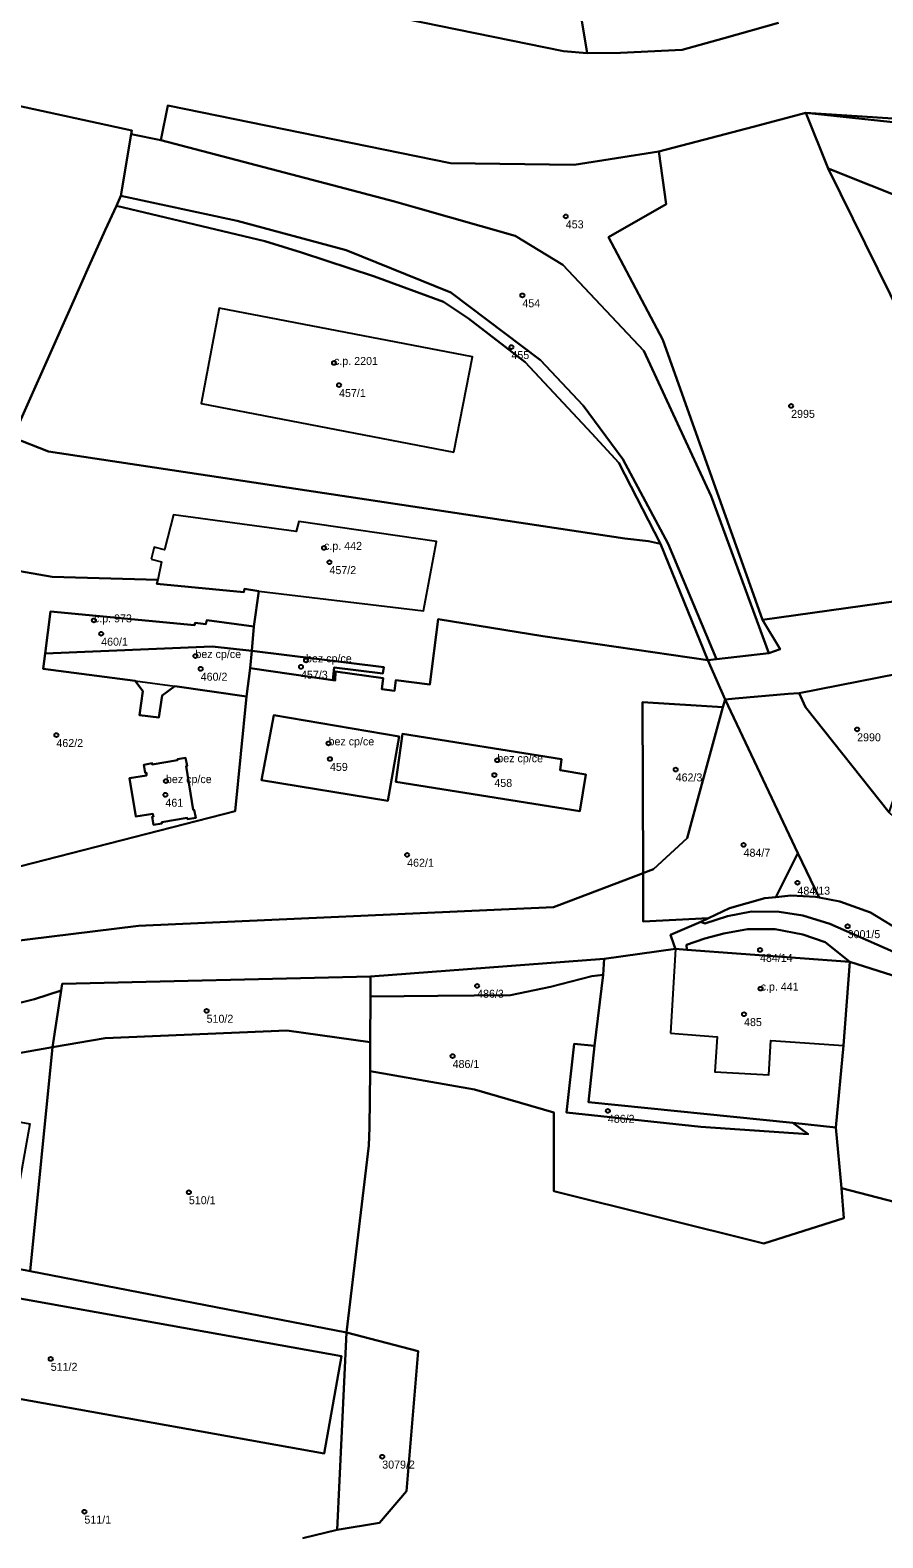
# Model space of a CAD drawing. Extents: x -878211 to -870363, y -1058464 to -1052522.
# Drawn here: x -874127.9 to -874021, y -1056425.6 to -1056236.7 of the extents above; entities that cross this region are included whole.
import ezdxf

# ---------------------------------------------------------------- set-up
doc = ezdxf.new("R2010")
doc.units = 0
for name, color, linetype in [('Vrstva 50', 7, 'Continuous'), ('Vrstva 51', 7, 'Continuous'), ('Vrstva 52', 7, 'Continuous')]:
    doc.layers.add(name, color=color, linetype=linetype)

msp = doc.modelspace()

# ---------------------------------------------------------------- linework, layer by layer
at = {"layer": 'Vrstva 50'}
for centre in [(-874060.75, -1056259.99994), (-874066.19, -1056269.88994), (-874067.56, -1056276.37994), (-874089.79, -1056278.35994), (-874089.16, -1056281.13994), (-874032.51, -1056283.74994), (-874091.04, -1056301.52994), (-874090.36, -1056303.32994), (-874119.88, -1056310.61994), (-874118.97, -1056312.29994), (-874107.16, -1056315.08994), (-874106.5, -1056316.68994), (-874093.93, -1056316.43994), (-874093.3, -1056315.62994), (-874024.24, -1056324.27994), (-874124.58, -1056324.99994), (-874090.48, -1056326.02994), (-874090.3, -1056327.98994), (-874069.33, -1056328.14994), (-874069.7, -1056329.99994), (-874046.98, -1056329.30994), (-874110.85, -1056330.75994), (-874110.92, -1056332.47994), (-874038.47, -1056338.74994), (-874080.63, -1056339.99994), (-874031.72, -1056343.49994), (-874025.43, -1056348.94994), (-874036.41, -1056351.91994), (-874071.86, -1056356.41994), (-874036.33, -1056356.76994), (-874105.76, -1056359.54994), (-874038.41, -1056359.96994), (-874074.93, -1056365.21994), (-874055.48, -1056372.08994), (-874107.98, -1056382.28994), (-874125.29, -1056403.16994), (-874083.75, -1056415.41994), (-874121.07, -1056422.31994)]:
    msp.add_circle(centre, 0.25, dxfattribs=at)
at = {"layer": 'Vrstva 51'}
for points in [[(-874059.11, -1056233.23), (-874064.36, -1056233.25), (-874065.94, -1056233.26), (-874106.31, -1056225.83), (-874114.6, -1056224.35), (-874120.49, -1056226.51), (-874127.68, -1056227.83), (-874142.65, -1056236.19), (-874138.49, -1056244.16), (-874126.68, -1056232.13), (-874109.62, -1056229.34), (-874061.05, -1056239.3), (-874058.08, -1056239.54)], [(-874079.57, -1056258.86), (-874067.1, -1056262.42), (-874061.1, -1056266.05), (-874050.97, -1056276.86), (-874042.54, -1056295.05), (-874035.32, -1056314.71), (-874033.87, -1056314.23), (-874036.08, -1056310.57), (-874048.58, -1056275.46), (-874055.38, -1056262.61), (-874048.16, -1056258.46), (-874049.09, -1056251.87), (-874059.72, -1056253.54), (-874075.21, -1056253.33), (-874110.6, -1056246.1), (-874111.48, -1056250.46), (-874089.99, -1056256.06), (-874082.23, -1056258.11)], [(-874049.09, -1056251.87), (-874048.16, -1056258.46), (-874055.38, -1056262.61), (-874048.58, -1056275.46), (-874036.08, -1056310.57), (-874017.31, -1056307.91), (-874017.32, -1056309.62), (-874007.97, -1056309.02), (-874002.08, -1056307.95), (-873993.82, -1056304.25), (-873999.93, -1056301.64), (-874017.02, -1056276.02), (-874027.88, -1056253.98), (-874030.65, -1056247.03), (-874037.26, -1056248.76), (-874042.53, -1056250.15)], [(-873797.24, -1056300.31), (-873896.52, -1056284.41), (-873978.91, -1056271.72), (-873994.77, -1056260.17), (-874013.14, -1056248.9), (-874030.65, -1056247.03), (-874027.88, -1056253.98), (-874017.16, -1056258.25), (-874000.36, -1056269.81), (-873980.12, -1056280.18), (-873897.49, -1056292.51), (-873788.4, -1056310.11), (-873790.45, -1056308.07), (-873795.73, -1056302.13)], [(-873797.24, -1056300.31), (-873819.79, -1056279.67), (-873848.06, -1056269.06), (-873855.46, -1056263.87), (-873865.64, -1056260.91), (-873876.47, -1056261.7), (-873908.1, -1056261.09), (-873916.49, -1056260.24), (-873969.22, -1056250.9), (-873996.05, -1056249.29), (-874030.65, -1056247.03), (-874013.14, -1056248.9), (-873994.77, -1056260.17), (-873978.91, -1056271.72), (-873896.52, -1056284.41)], [(-874116.49, -1056257.43), (-874101.93, -1056260.55), (-874088.26, -1056264.21), (-874075.17, -1056269.51), (-874063.93, -1056278.01), (-874058.57, -1056283.7), (-874053.6, -1056290.43), (-874047.93, -1056301.04), (-874041.87, -1056315.47), (-874035.32, -1056314.71), (-874042.54, -1056295.05), (-874050.97, -1056276.86), (-874061.1, -1056266.05), (-874067.1, -1056262.42), (-874079.57, -1056258.86), (-874082.23, -1056258.11), (-874089.99, -1056256.06), (-874111.48, -1056250.46), (-874115.23, -1056249.69)], [(-874017.16, -1056258.25), (-874027.88, -1056253.98), (-874017.02, -1056276.02), (-873999.93, -1056301.64), (-873993.82, -1056304.25), (-873980.12, -1056280.18), (-874000.36, -1056269.81)], [(-874117.05, -1056258.67), (-874098.46, -1056263.09), (-874093.85, -1056264.5), (-874084.7, -1056267.52), (-874076.09, -1056270.72), (-874072.94, -1056272.77), (-874065.86, -1056278.28), (-874057.5, -1056287.22), (-874054.11, -1056290.88), (-874048.88, -1056301.03), (-874042.96, -1056315.61), (-874041.87, -1056315.47), (-874047.93, -1056301.04), (-874053.6, -1056290.43), (-874058.57, -1056283.7), (-874063.93, -1056278.01), (-874075.17, -1056269.51), (-874088.26, -1056264.21), (-874101.93, -1056260.55), (-874116.49, -1056257.43)], [(-874122.76, -1056271.35), (-874123.64, -1056273.32), (-874130.06, -1056287.71), (-874125.56, -1056289.45), (-874053.37, -1056300.34), (-874050.4, -1056300.68), (-874048.88, -1056301.03), (-874054.11, -1056290.88), (-874057.5, -1056287.22), (-874065.86, -1056278.28), (-874072.94, -1056272.77), (-874076.09, -1056270.72), (-874084.7, -1056267.52), (-874093.85, -1056264.5), (-874098.46, -1056263.09), (-874117.05, -1056258.67), (-874118.47, -1056261.73), (-874120.51, -1056266.29), (-874121.47, -1056268.45)], [(-874100.74, -1056320.17), (-874102.19, -1056334.51), (-874138.68, -1056343.87), (-874136.61, -1056351.17), (-874136.39, -1056351.63), (-874114.3, -1056348.91), (-874062.31, -1056346.55), (-874061.62, -1056346.29), (-874051.06, -1056342.3), (-874051.12, -1056320.88), (-874041.05, -1056321.49), (-874040.79, -1056320.53), (-874042.96, -1056315.61), (-874063.63, -1056312.59), (-874076.74, -1056310.47), (-874077.79, -1056318.66), (-874082.04, -1056318.09), (-874082.2, -1056319.45), (-874083.82, -1056319.24), (-874083.65, -1056317.85), (-874089.61, -1056317.03), (-874089.66, -1056318.17), (-874089.96, -1056318.13), (-874100.28, -1056316.61)], [(-874107.29, -1056311.22), (-874125.32, -1056309.5), (-874125.99, -1056314.77), (-874105.06, -1056313.91), (-874100.1, -1056314.42), (-874099.84, -1056311.4), (-874105.75, -1056310.58), (-874105.84, -1056311.09), (-874107.2, -1056310.91)], [(-874113.77, -1056319.48), (-874114.18, -1056322.48), (-874111.73, -1056322.78), (-874111.32, -1056320.04), (-874109.74, -1056318.87), (-874100.74, -1056320.17), (-874100.28, -1056316.61), (-874100.1, -1056314.42), (-874105.06, -1056313.91), (-874125.99, -1056314.77), (-874126.24, -1056316.71), (-874114.71, -1056318.19)], [(-874089.96, -1056318.13), (-874089.76, -1056316.53), (-874083.67, -1056317.29), (-874083.57, -1056316.5), (-874100.1, -1056314.42), (-874100.28, -1056316.61)], [(-874031.51, -1056319.74), (-874030.73, -1056321.5), (-874020.22, -1056334.71), (-874016.52, -1056323.42), (-874016.65, -1056316.8)], [(-874044.19, -1056332.98), (-874041.05, -1056321.49), (-874051.12, -1056320.88), (-874051.06, -1056342.3), (-874050.43, -1056342.06), (-874049.76, -1056341.81), (-874045.54, -1056337.91)], [(-874034.44, -1056345.3), (-874031.66, -1056339.78), (-874040.79, -1056320.53), (-874041.05, -1056321.49), (-874044.19, -1056332.98), (-874045.54, -1056337.91), (-874049.76, -1056341.81), (-874050.43, -1056342.06), (-874051.06, -1056342.3), (-874051.04, -1056348.34), (-874042.85, -1056347.92), (-874040.22, -1056346.68), (-874035.79, -1056345.45)], [(-874081.62, -1056325.16), (-874097.34, -1056322.49), (-874098.87, -1056330.66), (-874083.03, -1056333.25)], [(-874081.62, -1056325.16), (-874083.03, -1056333.25), (-874098.87, -1056330.66), (-874097.34, -1056322.49)], [(-874061.47, -1056329.38), (-874061.27, -1056328.02), (-874081.2, -1056324.85), (-874082.05, -1056330.85), (-874058.98, -1056334.53), (-874058.24, -1056329.94)], [(-874061.47, -1056329.38), (-874058.24, -1056329.94), (-874058.98, -1056334.53), (-874082.05, -1056330.85), (-874081.2, -1056324.85), (-874061.27, -1056328.02)], [(-874113.31, -1056329.71), (-874113.28, -1056330.04), (-874115.42, -1056330.4), (-874114.64, -1056335.2), (-874112.48, -1056334.85), (-874112.42, -1056335.2), (-874112.58, -1056335.22), (-874112.41, -1056336.24), (-874111.39, -1056336.07), (-874111.36, -1056335.92), (-874108.19, -1056335.38), (-874108.17, -1056335.52), (-874107.11, -1056335.37), (-874107.3, -1056334.34), (-874107.43, -1056334.34), (-874108.34, -1056328.88), (-874108.2, -1056328.85), (-874108.39, -1056327.83), (-874109.42, -1056327.99), (-874109.42, -1056328.13), (-874112.58, -1056328.67), (-874112.6, -1056328.52), (-874113.64, -1056328.7), (-874113.46, -1056329.73)], [(-874113.31, -1056329.71), (-874113.46, -1056329.73), (-874113.64, -1056328.7), (-874112.6, -1056328.52), (-874112.58, -1056328.67), (-874109.42, -1056328.13), (-874109.42, -1056327.99), (-874108.39, -1056327.83), (-874108.2, -1056328.85), (-874108.34, -1056328.88), (-874107.43, -1056334.34), (-874107.3, -1056334.34), (-874107.11, -1056335.37), (-874108.17, -1056335.52), (-874108.19, -1056335.38), (-874111.36, -1056335.92), (-874111.39, -1056336.07), (-874112.41, -1056336.24), (-874112.58, -1056335.22), (-874112.42, -1056335.2), (-874112.48, -1056334.85), (-874114.64, -1056335.2), (-874115.42, -1056330.4), (-874113.28, -1056330.04)], [(-874034.44, -1056345.3), (-874032.55, -1056345.1), (-874029.45, -1056345.28), (-874028.99, -1056345.36), (-874031.66, -1056339.78)], [(-874042.85, -1056347.92), (-874043.84, -1056348.38), (-874043.31, -1056348.59), (-874040.47, -1056347.68), (-874037.48, -1056347.09), (-874034.01, -1056347.14), (-874031.03, -1056347.6), (-874027.65, -1056348.65), (-874011.71, -1056355.68), (-874010.74, -1056355.42), (-874013.39, -1056353.61), (-874018.19, -1056349.9), (-874022.58, -1056347.23), (-874026.42, -1056345.83), (-874028.99, -1056345.36), (-874029.45, -1056345.28), (-874032.55, -1056345.1), (-874034.44, -1056345.3), (-874035.79, -1056345.45), (-874040.22, -1056346.68)], [(-874045.59, -1056351.89), (-874025.16, -1056353.39), (-874028.26, -1056350.94), (-874031.05, -1056349.98), (-874034.51, -1056349.3), (-874037.96, -1056349.3), (-874040.93, -1056349.84), (-874043.34, -1056350.5), (-874045.62, -1056351.28)], [(-874025.94, -1056363.91), (-874025.16, -1056353.39), (-874045.59, -1056351.89), (-874047.01, -1056351.79), (-874055.94, -1056353.02), (-874056.06, -1056355.02), (-874057.15, -1056363.95), (-874057.92, -1056371), (-874032.3, -1056373.57), (-874026.9, -1056374.16)], [(-874055.94, -1056353.02), (-874085.23, -1056355.23), (-874085.23, -1056357.74), (-874076.8, -1056357.66), (-874067.66, -1056357.57), (-874062.67, -1056356.52), (-874057.5, -1056355.2), (-874056.06, -1056355.02)], [(-873996.96, -1056386.93), (-873996.37, -1056385.7), (-874001.54, -1056383.61), (-873998.1, -1056375.5), (-873993.66, -1056365.6), (-874016.36, -1056356.19), (-874025.16, -1056353.39), (-874025.94, -1056363.91), (-874026.9, -1056374.16), (-874026.22, -1056381.77), (-873998.01, -1056389.1)], [(-874085.23, -1056355.23), (-874123.85, -1056356.15), (-874123.97, -1056357), (-874125.06, -1056364.12), (-874118.48, -1056362.96), (-874095.71, -1056362.03), (-874085.26, -1056363.47), (-874085.23, -1056357.74)], [(-874026.22, -1056381.77), (-874026.9, -1056374.16), (-874032.3, -1056373.57), (-874030.38, -1056375.02), (-874043.83, -1056374.1), (-874060.65, -1056372.28), (-874059.69, -1056363.68), (-874057.15, -1056363.95), (-874056.06, -1056355.02), (-874057.5, -1056355.2), (-874062.67, -1056356.52), (-874067.66, -1056357.57), (-874076.8, -1056357.66), (-874085.23, -1056357.74), (-874085.26, -1056363.47), (-874085.27, -1056367.09), (-874072.2, -1056369.4), (-874062.24, -1056372.28), (-874062.24, -1056382.16), (-874035.94, -1056388.69), (-874025.92, -1056385.52)], [(-874125.06, -1056364.12), (-874127.85, -1056392.18), (-874088.23, -1056399.85), (-874085.45, -1056376.44), (-874085.34, -1056374.16), (-874085.27, -1056367.09), (-874085.26, -1056363.47), (-874095.71, -1056362.03), (-874118.48, -1056362.96)], [(-874032.3, -1056373.57), (-874057.92, -1056371), (-874057.15, -1056363.95), (-874059.69, -1056363.68), (-874060.65, -1056372.28), (-874043.83, -1056374.1), (-874030.38, -1056375.02)], [(-874131.1, -1056391.55), (-874127.85, -1056392.18), (-874125.06, -1056364.12), (-874145.98, -1056367.81), (-874154.41, -1056387.04), (-874143.29, -1056389.19), (-874140.06, -1056371.5), (-874127.89, -1056373.71)], [(-874131.1, -1056391.55), (-874143.29, -1056389.19), (-874145.95, -1056403.75), (-874133.69, -1056406.04), (-874133.94, -1056407.33), (-874091.04, -1056415), (-874088.86, -1056402.82), (-874131.74, -1056395.13)], [(-874089.4, -1056424.57), (-874084.09, -1056423.71), (-874080.72, -1056419.74), (-874079.26, -1056402.21), (-874088.23, -1056399.85)]]:
    msp.add_lwpolyline(points, close=True, dxfattribs=at)
for points in [[(-874034.08, -1056235.73), (-874040.92, -1056237.64), (-874046.18, -1056239.11), (-874053.89, -1056239.5), (-874058.08, -1056239.54), (-874061.05, -1056239.3), (-874109.62, -1056229.34)], [(-874126.68, -1056232.13), (-874138.49, -1056244.16), (-874136.86, -1056244.52), (-874115.14, -1056249.21), (-874115.23, -1056249.69), (-874111.48, -1056250.46), (-874110.6, -1056246.1), (-874075.21, -1056253.33), (-874059.72, -1056253.54), (-874049.09, -1056251.87), (-874042.53, -1056250.15), (-874037.26, -1056248.76), (-874030.65, -1056247.03), (-873996.05, -1056249.29), (-873969.22, -1056250.9), (-873916.49, -1056260.24), (-873908.1, -1056261.09), (-873876.47, -1056261.7), (-873865.64, -1056260.91)], [(-874059.11, -1056233.23), (-874058.08, -1056239.54), (-874053.89, -1056239.5), (-874046.18, -1056239.11), (-874040.92, -1056237.64), (-874034.08, -1056235.73)], [(-874130.06, -1056287.71), (-874123.64, -1056273.32), (-874122.76, -1056271.35), (-874121.47, -1056268.45), (-874120.51, -1056266.29), (-874118.47, -1056261.73), (-874117.05, -1056258.67), (-874116.49, -1056257.43), (-874115.23, -1056249.69), (-874115.14, -1056249.21), (-874136.86, -1056244.52)], [(-874132.55, -1056303.87), (-874125.1, -1056305.17), (-874111.89, -1056305.55), (-874112, -1056306.04), (-874101.09, -1056307.09), (-874101.03, -1056306.67), (-874099.22, -1056306.94), (-874099.84, -1056311.4), (-874100.1, -1056314.42), (-874083.57, -1056316.5), (-874083.67, -1056317.29), (-874089.76, -1056316.53), (-874089.96, -1056318.13), (-874089.66, -1056318.17), (-874089.61, -1056317.03), (-874083.65, -1056317.85), (-874083.82, -1056319.24), (-874082.2, -1056319.45), (-874082.04, -1056318.09), (-874077.79, -1056318.66), (-874076.74, -1056310.47), (-874063.63, -1056312.59), (-874042.96, -1056315.61), (-874048.88, -1056301.03), (-874050.4, -1056300.68), (-874053.37, -1056300.34), (-874125.56, -1056289.45), (-874130.06, -1056287.71)], [(-874138.68, -1056343.87), (-874102.19, -1056334.51), (-874100.74, -1056320.17), (-874109.74, -1056318.87), (-874111.32, -1056320.04), (-874111.73, -1056322.78), (-874114.18, -1056322.48), (-874113.77, -1056319.48), (-874114.71, -1056318.19), (-874126.24, -1056316.71), (-874125.99, -1056314.77), (-874125.32, -1056309.5), (-874107.29, -1056311.22), (-874107.2, -1056310.91), (-874105.84, -1056311.09), (-874105.75, -1056310.58), (-874099.84, -1056311.4), (-874099.22, -1056306.94), (-874101.03, -1056306.67), (-874101.09, -1056307.09), (-874112, -1056306.04), (-874111.89, -1056305.55), (-874125.1, -1056305.17), (-874132.55, -1056303.87)], [(-874017.31, -1056307.91), (-874036.08, -1056310.57), (-874033.87, -1056314.23), (-874035.32, -1056314.71), (-874041.87, -1056315.47), (-874042.96, -1056315.61), (-874040.79, -1056320.53), (-874039.53, -1056320.42), (-874032.89, -1056319.84), (-874031.51, -1056319.74), (-874016.65, -1056316.8)], [(-873856.57, -1056433.51), (-874008.04, -1056345.96), (-874020.22, -1056334.71), (-874030.73, -1056321.5), (-874031.51, -1056319.74), (-874032.89, -1056319.84), (-874039.53, -1056320.42), (-874040.79, -1056320.53), (-874031.66, -1056339.78), (-874028.99, -1056345.36), (-874026.42, -1056345.83), (-874022.58, -1056347.23), (-874018.19, -1056349.9), (-874013.39, -1056353.61), (-874010.74, -1056355.42), (-874005.68, -1056358.3), (-874002.94, -1056359.69), (-873989.84, -1056366.2), (-873969.5, -1056378.1), (-873960.26, -1056383.5), (-873960.13, -1056383.28), (-873955.28, -1056386.42), (-873926.22, -1056403.42), (-873876.13, -1056432)], [(-874136.62, -1056429.22), (-874154.14, -1056399.02), (-874157.21, -1056398.32), (-874158.49, -1056395.01), (-874159.82, -1056388.79), (-874160.5, -1056381.43), (-874159.19, -1056376.12), (-874153.25, -1056366.1), (-874145.97, -1056362.7), (-874127.34, -1056358.1), (-874123.97, -1056357), (-874123.85, -1056356.15), (-874085.23, -1056355.23), (-874055.94, -1056353.02), (-874047.01, -1056351.79), (-874047.16, -1056351.36), (-874047.64, -1056350.04), (-874043.84, -1056348.38), (-874042.85, -1056347.92), (-874051.04, -1056348.34), (-874051.06, -1056342.3), (-874061.62, -1056346.29)], [(-874061.62, -1056346.29), (-874062.31, -1056346.55), (-874114.3, -1056348.91), (-874136.39, -1056351.63), (-874136.32, -1056352.21), (-874138.64, -1056352.97), (-874137.97, -1056356.21), (-874158.32, -1056361.7), (-874163.32, -1056361.25), (-874193.12, -1056364.56), (-874196.14, -1056364.9), (-874193.03, -1056372.08), (-874189.31, -1056371.79)], [(-874011.71, -1056355.68), (-874027.65, -1056348.65), (-874031.03, -1056347.6), (-874034.01, -1056347.14), (-874037.48, -1056347.09), (-874040.47, -1056347.68), (-874043.31, -1056348.59), (-874043.84, -1056348.38), (-874047.64, -1056350.04), (-874047.16, -1056351.36), (-874047.01, -1056351.79), (-874045.59, -1056351.89), (-874045.62, -1056351.28), (-874043.34, -1056350.5), (-874040.93, -1056349.84), (-874037.96, -1056349.3), (-874034.51, -1056349.3), (-874031.05, -1056349.98), (-874028.26, -1056350.94), (-874025.16, -1056353.39), (-874016.36, -1056356.19)], [(-874145.98, -1056367.81), (-874125.06, -1056364.12), (-874123.97, -1056357), (-874127.34, -1056358.1), (-874145.97, -1056362.7)], [(-873998.01, -1056389.1), (-874026.22, -1056381.77), (-874025.92, -1056385.52), (-874035.94, -1056388.69), (-874062.24, -1056382.16), (-874062.24, -1056372.28), (-874072.2, -1056369.4), (-874085.27, -1056367.09), (-874085.34, -1056374.16), (-874085.45, -1056376.44), (-874088.23, -1056399.85), (-874079.26, -1056402.21), (-874080.72, -1056419.74), (-874084.09, -1056423.71), (-874089.4, -1056424.57), (-874093.72, -1056425.61)], [(-874093.72, -1056425.61), (-874089.4, -1056424.57), (-874088.23, -1056399.85), (-874127.85, -1056392.18), (-874131.1, -1056391.55)], [(-874131.74, -1056395.13), (-874088.86, -1056402.82), (-874091.04, -1056415), (-874133.94, -1056407.33)]]:
    msp.add_lwpolyline(points, dxfattribs=at)
at = {"layer": 'Vrstva 52'}
for points in [[(-874074.76, -1056289.53), (-874072.44, -1056277.58), (-874104.18, -1056271.51), (-874106.45, -1056283.45)], [(-874112.7, -1056302.95), (-874111.41, -1056303.3), (-874111.89, -1056305.55), (-874112, -1056306.04), (-874101.09, -1056307.09), (-874101.03, -1056306.67), (-874099.22, -1056306.94), (-874078.58, -1056309.44), (-874076.96, -1056300.72), (-874094.22, -1056298.22), (-874094.55, -1056299.46), (-874109.91, -1056297.41), (-874111.05, -1056301.76), (-874112.34, -1056301.46)], [(-874125.99, -1056314.77), (-874105.06, -1056313.91), (-874100.1, -1056314.42), (-874099.84, -1056311.4), (-874105.75, -1056310.58), (-874105.84, -1056311.09), (-874107.2, -1056310.91), (-874107.29, -1056311.22), (-874125.32, -1056309.5)], [(-874126.24, -1056316.71), (-874114.71, -1056318.19), (-874109.74, -1056318.87), (-874100.74, -1056320.17), (-874100.28, -1056316.61), (-874100.1, -1056314.42), (-874105.06, -1056313.91), (-874125.99, -1056314.77)], [(-874100.1, -1056314.42), (-874100.28, -1056316.61), (-874089.96, -1056318.13), (-874089.76, -1056316.53), (-874083.67, -1056317.29), (-874083.57, -1056316.5)], [(-874098.87, -1056330.66), (-874083.03, -1056333.25), (-874081.62, -1056325.16), (-874097.34, -1056322.49)], [(-874081.2, -1056324.85), (-874082.05, -1056330.85), (-874058.98, -1056334.53), (-874058.24, -1056329.94), (-874061.47, -1056329.38), (-874061.27, -1056328.02)], [(-874115.42, -1056330.4), (-874114.64, -1056335.2), (-874112.48, -1056334.85), (-874112.42, -1056335.2), (-874112.58, -1056335.22), (-874112.41, -1056336.24), (-874111.39, -1056336.07), (-874111.36, -1056335.92), (-874108.19, -1056335.38), (-874108.17, -1056335.52), (-874107.11, -1056335.37), (-874107.3, -1056334.34), (-874107.43, -1056334.34), (-874108.34, -1056328.88), (-874108.2, -1056328.85), (-874108.39, -1056327.83), (-874109.42, -1056327.99), (-874109.42, -1056328.13), (-874112.58, -1056328.67), (-874112.6, -1056328.52), (-874113.64, -1056328.7), (-874113.46, -1056329.73), (-874113.31, -1056329.71), (-874113.28, -1056330.04)], [(-874047.62, -1056362.33), (-874041.77, -1056362.79), (-874042.09, -1056367.18), (-874035.3, -1056367.56), (-874035.06, -1056363.25), (-874025.94, -1056363.91), (-874025.16, -1056353.39), (-874045.59, -1056351.89), (-874047.01, -1056351.79)]]:
    msp.add_lwpolyline(points, close=True, dxfattribs=at)

# ---------------------------------------------------------------- texts
at = {"layer": 'Vrstva 50'}
for s, p in [('453', (-874060.75, -1056261.489)), ('454', (-874066.19, -1056271.379)), ('455', (-874067.56, -1056277.869)), ('c.p. 2201', (-874089.79, -1056278.61)), ('457/1', (-874089.16, -1056282.629)), ('2995', (-874032.51, -1056285.239)), ('c.p. 442', (-874091.04, -1056301.78)), ('457/2', (-874090.36, -1056304.819)), ('c.p. 973', (-874119.88, -1056310.87)), ('460/1', (-874118.97, -1056313.789)), ('bez cp/ce', (-874107.16, -1056315.34)), ('bez cp/ce', (-874093.3, -1056315.879)), ('460/2', (-874106.5, -1056318.179)), ('457/3', (-874093.93, -1056317.929)), ('462/2', (-874124.58, -1056326.489)), ('bez cp/ce', (-874090.48, -1056326.28)), ('2990', (-874024.24, -1056325.769)), ('bez cp/ce', (-874069.33, -1056328.399)), ('459', (-874090.3, -1056329.479)), ('462/3', (-874046.98, -1056330.799)), ('bez cp/ce', (-874110.85, -1056331.01)), ('458', (-874069.7, -1056331.489)), ('461', (-874110.92, -1056333.969)), ('484/7', (-874038.47, -1056340.239)), ('462/1', (-874080.63, -1056341.489)), ('484/13', (-874031.72, -1056344.989)), ('3001/5', (-874025.43, -1056350.439)), ('484/14', (-874036.41, -1056353.409)), ('c.p. 441', (-874036.33, -1056357.02)), ('486/3', (-874071.86, -1056357.909)), ('510/2', (-874105.76, -1056361.039)), ('485', (-874038.41, -1056361.459)), ('486/1', (-874074.93, -1056366.709)), ('486/2', (-874055.48, -1056373.579)), ('510/1', (-874107.98, -1056383.779)), ('511/2', (-874125.29, -1056404.659)), ('3079/2', (-874083.75, -1056416.909)), ('511/1', (-874121.07, -1056423.809))]:
    msp.add_text(s, height=0.999996, dxfattribs=at).set_placement(p)

doc.saveas('drawing.dxf')
